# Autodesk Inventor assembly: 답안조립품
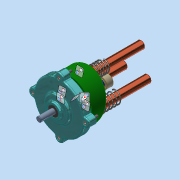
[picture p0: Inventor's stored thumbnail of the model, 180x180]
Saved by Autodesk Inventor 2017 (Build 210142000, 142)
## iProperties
Part Number: 답안조립품
Material: 일반
Document SubType Name: Assembly
Designer: MRC
Mass: 1236.64 g
Surface Area: 1770.13 cm^2
Volume: 433.791 cm^3
Density: 2.85077 g/cm^3
Author: MRC
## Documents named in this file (14)
- C:\Users\MRC\Desktop\610708V1001\답안조립품.iam
- C:\Users\MRC\Desktop\610708V1001\본체.ipt
- C:\Users\MRC\Desktop\610708V1001\가변스프링-01.ipt
- C:\Users\MRC\Desktop\610708V1001\가변스프링-02.ipt
- C:\Users\MRC\Desktop\610708V1001\가변스프링-03.ipt
- C:\Users\MRC\Desktop\610708V1001\멈춤링 10 x 1.ipt
- C:\Users\MRC\Desktop\610708V1001\멈춤링 22 x 1.2.ipt
- C:\Users\MRC\Desktop\610708V1001\메인 축.ipt
- C:\Users\MRC\Desktop\610708V1001\베어링 NA 4900.ipt
- C:\Users\MRC\Desktop\610708V1001\볼트 M5.ipt
- C:\Users\MRC\Desktop\610708V1001\슬라이드 축.ipt
- C:\Users\MRC\Desktop\610708V1001\오일실.ipt
- C:\Users\MRC\Desktop\610708V1001\커버.ipt
- C:\Users\MRC\Desktop\610708V1001\판캠.ipt
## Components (3 placed, 3 different names)
1. 가변스프링-01:1
2. 가변스프링-02:1
3. 가변스프링-03:1
